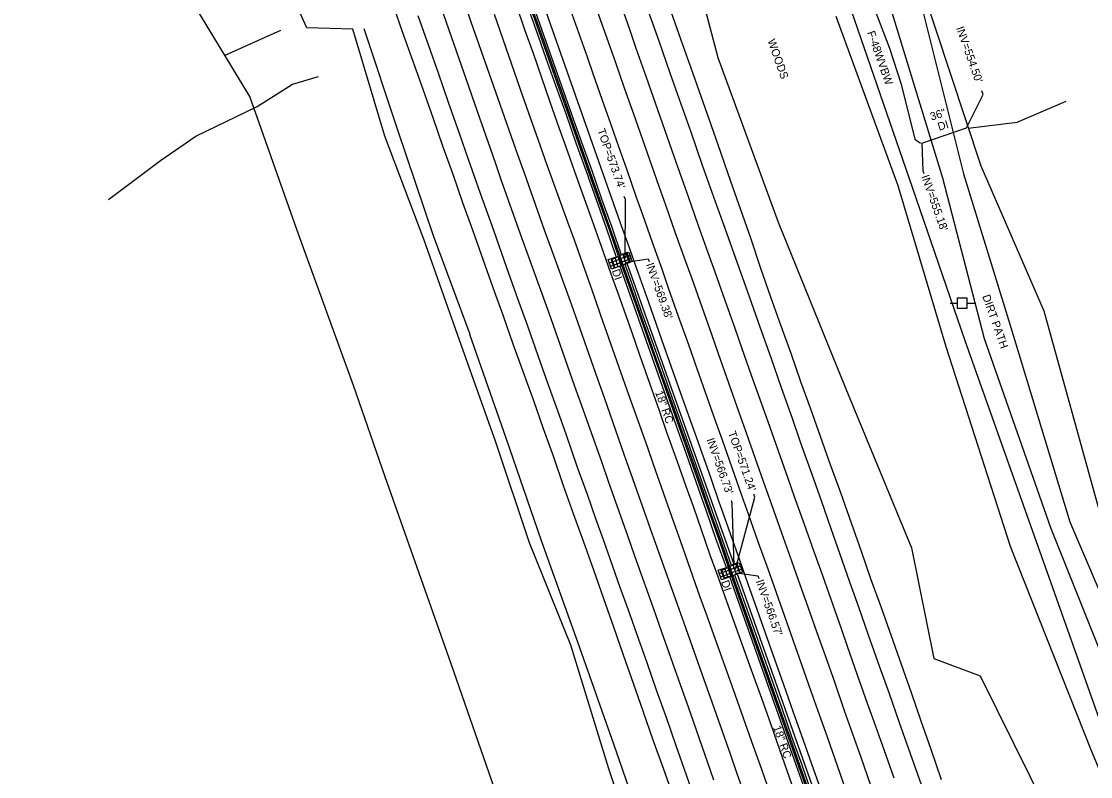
# Model space of a CAD drawing. Extents: x 2004847 to 2009016, y 1134161 to 1140101.
# Drawn here: x 2005873 to 2006408, y 1136162 to 1136539 of the extents above; entities that cross this region are included whole.
import ezdxf

# ---------------------------------------------------------------- set-up
doc = ezdxf.new("R2010")
doc.units = 0
for name, color, linetype in [('RD_EX_Conc', 7, 'Continuous'), ('RD_EX_DR_Inlet', 7, 'Continuous'), ('RD_EX_DR_Inlet_txCode', 7, 'Continuous'), ('RD_EX_DR_Pipe', 7, 'Continuous'), ('RD_EX_DR_Pipe_txCode', 7, 'Continuous'), ('RD_EX_Driveway', 7, 'Continuous'), ('RD_EX_Fence_Other', 7, 'Continuous'), ('RD_EX_H2O', 7, 'Continuous'), ('RD_EX_Pavement_Markings', 7, 'Continuous'), ('RD_EX_Road', 7, 'Continuous'), ('RD_EX_UT', 7, 'Continuous'), ('RD_EX_VEG', 7, 'Continuous'), ('RD_Sketch3', 7, 'Continuous')]:
    doc.layers.add(name, color=color, linetype=linetype)

msp = doc.modelspace()

# ---------------------------------------------------------------- linework, layer by layer
at = {"layer": 'RD_EX_Conc'}
for points in [[(2006126.82, 1136548.76), (2006131.84, 1136534.6), (2006136.85, 1136520.47), (2006141.87, 1136506.33), (2006146.87, 1136492.19), (2006151.89, 1136478.06), (2006156.89, 1136463.92), (2006161.94, 1136449.8), (2006166.95, 1136435.61), (2006171.9, 1136421.48), (2006176.97, 1136407.37), (2006181.96, 1136393.22), (2006186.97, 1136379.09), (2006191.97, 1136364.99), (2006197.01, 1136350.77), (2006202, 1136336.67), (2006206.99, 1136322.55), (2006212.01, 1136308.42), (2006216.96, 1136294.26), (2006221.99, 1136280.14), (2006226.92, 1136265.96), (2006231.91, 1136251.8), (2006236.91, 1136237.66), (2006241.89, 1136223.49), (2006246.86, 1136209.37), (2006251.86, 1136195.19), (2006256.85, 1136181.1), (2006261.87, 1136166.89), (2006266.82, 1136152.8)], [(2006127.45, 1136548.98), (2006132.48, 1136534.83), (2006137.49, 1136520.69), (2006142.48, 1136506.55), (2006147.52, 1136492.42), (2006152.53, 1136478.29), (2006157.53, 1136464.14), (2006162.56, 1136450.02), (2006167.57, 1136435.83), (2006172.54, 1136421.71), (2006177.6, 1136407.59), (2006182.59, 1136393.44), (2006187.59, 1136379.31), (2006192.59, 1136365.21), (2006197.65, 1136351.01), (2006202.62, 1136336.89), (2006207.63, 1136322.77), (2006212.62, 1136308.63), (2006217.58, 1136294.48), (2006222.62, 1136280.35), (2006227.56, 1136266.18), (2006232.54, 1136252.02), (2006237.53, 1136237.88), (2006242.53, 1136223.72), (2006247.51, 1136209.6), (2006252.51, 1136195.42), (2006257.53, 1136181.34), (2006262.53, 1136167.13), (2006267.48, 1136153.03)]]:
    msp.add_lwpolyline(points, dxfattribs=at)
at = {"layer": 'RD_EX_DR_Inlet'}
for p, q in [((2006175.57, 1136423.28), (2006177.19, 1136418.55)), ((2006167.31, 1136418.47), (2006172.04, 1136420.09)), ((2006167.86, 1136416.86), (2006172.59, 1136418.48)), ((2006168.37, 1136420.63), (2006169.99, 1136415.9)), ((2006169.98, 1136421.18), (2006171.6, 1136416.45)), ((2006172.9, 1136420.57), (2006177.63, 1136422.19)), ((2006173.45, 1136418.96), (2006178.18, 1136420.58)), ((2006173.96, 1136422.73), (2006175.58, 1136418)), ((2006230.66, 1136268.04), (2006232.28, 1136263.31)), ((2006222.23, 1136263.18), (2006226.96, 1136264.8)), ((2006222.79, 1136261.57), (2006227.52, 1136263.19)), ((2006223.29, 1136265.34), (2006224.91, 1136260.61)), ((2006224.9, 1136265.89), (2006226.52, 1136261.16)), ((2006227.99, 1136265.33), (2006232.72, 1136266.95)), ((2006228.54, 1136263.72), (2006233.27, 1136265.35)), ((2006229.05, 1136267.49), (2006230.67, 1136262.76))]:
    msp.add_line(p, q, dxfattribs=at)
for points in [[(2006173.97, 1136417.45), (2006172.35, 1136422.18), (2006177.08, 1136423.8), (2006178.7, 1136419.07)], [(2006168.38, 1136415.35), (2006166.76, 1136420.08), (2006171.49, 1136421.7), (2006173.11, 1136416.97)], [(2006229.06, 1136262.21), (2006227.44, 1136266.94), (2006232.17, 1136268.56), (2006233.79, 1136263.83)], [(2006223.31, 1136260.06), (2006221.68, 1136264.79), (2006226.41, 1136266.41), (2006228.03, 1136261.68)]]:
    msp.add_lwpolyline(points, close=True, dxfattribs=at)
at = {"layer": 'RD_EX_DR_Inlet_txCode'}
for points in [[(2006345.77, 1136485.85), (2006354.14, 1136502.56), (2006353.5, 1136504.37)], [(2006323.46, 1136478.34), (2006324.03, 1136464.51), (2006324.52, 1136463.11)], [(2006175.25, 1136420.54), (2006175.32, 1136450.13), (2006174.77, 1136451.67)], [(2006175.89, 1136418.77), (2006186.64, 1136420.47), (2006187.11, 1136419.14)], [(2006230.32, 1136265.36), (2006240, 1136301.41), (2006239.48, 1136302.88)], [(2006229.63, 1136267.31), (2006228.65, 1136298.35), (2006228.26, 1136299.45)], [(2006230.99, 1136263.47), (2006241.48, 1136261.95), (2006241.93, 1136260.68)]]:
    msp.add_lwpolyline(points, dxfattribs=at)
at = {"layer": 'RD_EX_DR_Pipe'}
for p, q in [((2006323.46, 1136478.34), (2006345.77, 1136485.85)), ((2006175.89, 1136418.77), (2006229.63, 1136267.31)), ((2006230.99, 1136263.47), (2006287.37, 1136104.14))]:
    msp.add_line(p, q, dxfattribs=at)
at = {"layer": 'RD_EX_Driveway'}
for points in [[(2006320.55, 1136558.36), (2006344.22, 1136462.95), (2006367.47, 1136387.76), (2006397.5, 1136288.99), (2006440.84, 1136187.25), (2006478.74, 1136083.47), (2006518.32, 1135988.65), (2006563.43, 1135904.15)], [(2006551.41, 1135897.85), (2006505.13, 1135983.38), (2006469.38, 1136080.46), (2006429.34, 1136182.74), (2006387.99, 1136286.09), (2006354.86, 1136380.53), (2006334.03, 1136460.8), (2006306.37, 1136551.19)]]:
    msp.add_lwpolyline(points, dxfattribs=at)
at = {"layer": 'RD_EX_Fence_Other'}
for points in [[(2006150.07, 1136043.34), (2006115.42, 1136139.93), (2006088.15, 1136218.09), (2006055.25, 1136311.48), (2006039.49, 1136357.1), (2006011.97, 1136432.75), (2005987.61, 1136501.5), (2005957.81, 1136550.91), (2005937.54, 1136641.63), (2005905.9, 1136732.88), (2005873.43, 1136823.78)], [(2006288.09, 1136544.58), (2006318.68, 1136456.24), (2006344.96, 1136379.7), (2006379.57, 1136282.04), (2006416.49, 1136178.27), (2006490.52, 1135969.29)]]:
    msp.add_lwpolyline(points, dxfattribs=at)
at = {"layer": 'RD_EX_H2O'}
msp.add_line((2005975.27, 1136522.16), (2006003.16, 1136534.73), dxfattribs=at)
for points in [[(2006272.18, 1136630.95), (2006272.22, 1136630.81), (2006281.18, 1136599.43), (2006285.93, 1136585.09), (2006298.47, 1136548.7), (2006307.39, 1136525.67), (2006313.2, 1136507.7), (2006320, 1136480.19), (2006322.75, 1136478.28)], [(2006044.58, 1136535.51), (2006061.38, 1136484.99), (2006079.26, 1136432.16), (2006097.52, 1136382.87), (2006097.47, 1136382.84), (2006115.58, 1136331.03), (2006133.19, 1136279.75), (2006151.31, 1136229.01), (2006169.58, 1136177.63)], [(2005917.01, 1136450.16), (2005943.01, 1136469.65), (2005960.66, 1136481.73), (2005991.29, 1136496.61), (2006008.97, 1136507.77), (2006021.87, 1136511.55)], [(2006346.55, 1136485.76), (2006371.1, 1136488.8), (2006395.68, 1136499.17)], [(2006169.58, 1136177.63), (2006207.33, 1136068.49), (2006240.4, 1135975.91), (2006259.05, 1135923.24), (2006279.18, 1135873.19), (2006283.21, 1135863.56), (2006290.81, 1135841.34), (2006301.16, 1135806.7), (2006317.11, 1135762.46), (2006327.77, 1135727.04)]]:
    msp.add_lwpolyline(points, dxfattribs=at)
at = {"layer": 'RD_EX_Pavement_Markings'}
for points in [[(2006144.73, 1136553.93), (2006150.43, 1136537.67), (2006156.13, 1136521.4), (2006159.25, 1136512.51), (2006163.57, 1136500.28), (2006167.89, 1136488.04), (2006170.88, 1136479.37), (2006175.81, 1136465.36), (2006180.73, 1136451.35), (2006183.81, 1136442.6), (2006188.71, 1136428.81), (2006193.61, 1136415.02), (2006196.74, 1136406.02), (2006201.76, 1136391.81), (2006206.78, 1136377.61), (2006210.03, 1136368.49), (2006215.21, 1136353.78), (2006220.39, 1136339.08), (2006223.62, 1136329.98), (2006228.52, 1136316.19), (2006233.41, 1136302.39), (2006236.7, 1136293.05), (2006241.58, 1136279.27), (2006246.46, 1136265.49), (2006249.42, 1136256.95), (2006254.79, 1136241.81), (2006260.16, 1136226.68), (2006263.11, 1136218.23), (2006268.05, 1136204.31), (2006272.98, 1136190.39), (2006276.1, 1136181.52), (2006281.31, 1136166.68), (2006286.53, 1136151.84)], [(2006094.82, 1136548.31), (2006098.06, 1136538.91), (2006108.27, 1136510.01), (2006111.6, 1136500.62), (2006121.45, 1136472.59), (2006124.73, 1136463.39), (2006134.78, 1136434.88), (2006138.15, 1136425.46), (2006148.31, 1136397.39), (2006151.49, 1136388.46), (2006161.41, 1136360.52), (2006164.68, 1136351.15), (2006174.59, 1136322.82), (2006177.93, 1136313.43), (2006187.67, 1136285.66), (2006190.94, 1136276.4), (2006201.13, 1136247.8), (2006204.48, 1136238.58), (2006214.54, 1136210.17), (2006217.63, 1136201.33), (2006227.6, 1136173.06), (2006230.87, 1136163.75), (2006241.16, 1136134.53)], [(2006120.32, 1136548.39), (2006125.13, 1136534.55), (2006129.17, 1136523.28), (2006133.34, 1136511.03), (2006137.41, 1136499.38), (2006141.28, 1136488.41), (2006146.42, 1136474.04), (2006149.89, 1136464.14), (2006153.05, 1136455.29), (2006159.33, 1136437.53), (2006164.18, 1136424.02), (2006168.11, 1136413.02), (2006172.69, 1136400.13), (2006178.3, 1136384.11), (2006182.44, 1136372.43), (2006187.42, 1136358.29), (2006192.23, 1136344.7), (2006195.76, 1136334.4), (2006201.24, 1136319.12), (2006205.48, 1136306.87), (2006209.28, 1136296.33), (2006213.18, 1136285.12), (2006217.59, 1136272.54), (2006221.46, 1136261.77), (2006225.06, 1136251.7), (2006229.06, 1136240.56), (2006233.53, 1136228.01), (2006238.18, 1136215.12), (2006243.26, 1136200.88), (2006247.76, 1136188.26), (2006252.54, 1136174.66), (2006255.84, 1136165.21), (2006259.8, 1136153.76)], [(2006134.46, 1136547.45), (2006172.52, 1136438.91), (2006176.48, 1136427.89), (2006181.66, 1136413.28), (2006186.64, 1136399.28), (2006193.39, 1136380.22), (2006198.19, 1136366.4), (2006203.73, 1136351.06), (2006210.69, 1136331.44), (2006217.96, 1136310.78), (2006222.07, 1136299.06), (2006223.98, 1136293.57), (2006227.92, 1136282.63), (2006232.32, 1136270.05), (2006236.53, 1136258.1), (2006241, 1136245.44), (2006245.17, 1136233.6), (2006249.85, 1136220.44), (2006254.32, 1136207.72), (2006259.07, 1136194.42), (2006264.11, 1136179.95), (2006268.38, 1136168.14), (2006275.31, 1136148.35)], [(2006172.29, 1136549.4), (2006177.28, 1136535.18), (2006180.53, 1136525.73), (2006185.44, 1136511.81), (2006190.35, 1136497.89), (2006193.67, 1136488.4), (2006198.52, 1136474.66), (2006203.36, 1136460.93), (2006206.62, 1136451.54), (2006211.53, 1136437.57), (2006216.44, 1136423.6), (2006219.94, 1136414.01), (2006224.95, 1136399.88), (2006229.95, 1136385.74), (2006233.28, 1136376.09), (2006238.19, 1136362.33), (2006243.09, 1136348.57), (2006246.42, 1136339.11), (2006251.46, 1136325.02), (2006256.5, 1136310.92), (2006259.72, 1136301.75), (2006264.61, 1136287.93), (2006269.51, 1136274.11), (2006272.78, 1136264.98), (2006277.95, 1136250.35), (2006283.13, 1136235.72), (2006286.22, 1136226.83), (2006291.2, 1136212.63), (2006296.18, 1136198.43), (2006299.5, 1136189.27), (2006304.5, 1136175.2), (2006309.51, 1136161.14)], [(2006071.6, 1136542.04), (2006076.82, 1136527), (2006081.69, 1136513.37), (2006086.77, 1136498.83), (2006092.19, 1136483.34), (2006096.73, 1136470.22), (2006102.72, 1136453.32), (2006109.31, 1136434.78), (2006115.94, 1136416.07), (2006121.35, 1136400.69), (2006126.33, 1136386.95), (2006131.58, 1136372.08), (2006136.62, 1136357.91), (2006141.37, 1136344.65), (2006145.67, 1136332.43), (2006151.09, 1136316.81), (2006156.17, 1136302.78), (2006160.44, 1136290.73), (2006164.17, 1136280.26), (2006168.81, 1136266.94), (2006172.55, 1136256.37), (2006176.65, 1136244.96), (2006181.93, 1136230.32), (2006186, 1136218.71), (2006190.71, 1136205.14), (2006195.96, 1136190.37), (2006200.53, 1136177.21), (2006205.64, 1136162.64), (2006211.09, 1136147.29)], [(2006083.86, 1136543.99), (2006087.01, 1136534.95), (2006096.94, 1136506.67), (2006100.08, 1136497.52), (2006110.03, 1136469.13), (2006113.1, 1136460.1), (2006123.56, 1136430.67), (2006126.66, 1136421.9), (2006136.98, 1136393.53), (2006140.15, 1136384.4), (2006149.95, 1136356.8), (2006153.2, 1136347.59), (2006163.49, 1136318.61), (2006166.73, 1136309.3), (2006176.49, 1136281.61), (2006179.72, 1136272.58), (2006190.17, 1136243.18), (2006193.41, 1136234.07), (2006203.49, 1136205.46), (2006206.67, 1136196.54), (2006216.23, 1136169.19), (2006219.41, 1136160.03)], [(2006109.64, 1136542.66), (2006119.64, 1136513.92), (2006122.87, 1136504.7), (2006132.7, 1136476.85), (2006136.02, 1136467.44), (2006146.41, 1136438.95), (2006149.64, 1136429.93), (2006159.64, 1136401.64), (2006162.9, 1136392.35), (2006172.87, 1136364.06), (2006176.1, 1136355.01), (2006186.14, 1136326.68), (2006189.27, 1136317.76), (2006199.32, 1136289.08), (2006202.62, 1136279.66), (2006212.58, 1136251.61), (2006215.87, 1136242.56), (2006226.05, 1136214.05), (2006229.15, 1136205.28), (2006239.22, 1136176.84), (2006242.45, 1136167.72), (2006252.54, 1136139.29)], [(2006161.69, 1136542.91), (2006166.84, 1136528.35), (2006170.15, 1136519.04), (2006174.74, 1136505.94), (2006179.33, 1136492.84), (2006182.68, 1136483.36), (2006187.35, 1136470.09), (2006192.02, 1136456.81), (2006195.35, 1136447.36), (2006200.25, 1136433.51), (2006205.15, 1136419.66), (2006208.44, 1136410.58), (2006213.45, 1136396.46), (2006218.46, 1136382.33), (2006221.66, 1136373.22), (2006226.86, 1136358.53), (2006232.05, 1136343.84), (2006235.29, 1136334.45), (2006240.17, 1136320.71), (2006245.05, 1136306.98), (2006248.28, 1136297.65), (2006253.29, 1136283.56), (2006258.3, 1136269.46), (2006261.51, 1136260.5), (2006266.66, 1136245.97), (2006271.81, 1136231.44), (2006275.13, 1136222.15), (2006279.92, 1136208.48), (2006284.71, 1136194.81), (2006288.05, 1136185.35), (2006292.95, 1136171.41), (2006297.85, 1136157.46)], [(2006323.36, 1136157.6), (2006317.84, 1136173.05), (2006312.36, 1136188.5), (2006307.08, 1136203.61), (2006302.5, 1136216.4), (2006296.85, 1136232.45), (2006291.97, 1136246.29), (2006287.53, 1136258.94), (2006282.49, 1136273.21), (2006278.12, 1136285.56), (2006273.27, 1136299.46), (2006268.6, 1136312.69), (2006263.05, 1136328.37), (2006258.77, 1136340.66), (2006253.38, 1136355.96), (2006248.1, 1136370.9), (2006242.65, 1136386.25), (2006237.3, 1136401.5), (2006232.12, 1136415.93), (2006225.23, 1136435.56), (2006220.38, 1136448.98), (2006213.76, 1136467.6), (2006208.14, 1136483.82), (2006202.39, 1136500.07), (2006197.68, 1136513.3), (2006192.13, 1136529.22), (2006186.85, 1136544.1)]]:
    msp.add_lwpolyline(points, dxfattribs=at)
at = {"layer": 'RD_EX_Road'}
msp.add_line((2006223.14, 1136264.76), (2006225.88, 1136265.8), dxfattribs=at)
for points in [[(2006117.95, 1136578.72), (2006118.33, 1136577.63), (2006123.3, 1136563.48), (2006128.35, 1136549.35), (2006133.36, 1136535.21), (2006138.37, 1136521.07), (2006143.36, 1136506.93), (2006148.41, 1136492.81), (2006153.45, 1136478.68), (2006158.59, 1136464.59), (2006163.42, 1136450.39), (2006168.46, 1136436.23), (2006173.24, 1136422.52)], [(2006115.39, 1136577.85), (2006115.54, 1136577.38), (2006120.52, 1136563.22), (2006125.58, 1136549.07), (2006130.6, 1136534.99), (2006135.61, 1136520.77), (2006140.62, 1136506.67), (2006145.63, 1136492.55), (2006150.53, 1136478.4), (2006155.62, 1136464.29), (2006160.66, 1136450.15), (2006165.63, 1136436.02), (2006170.61, 1136421.87), (2006170.87, 1136421.15)], [(2006059.15, 1136547.64), (2006063.98, 1136533.49), (2006069.02, 1136519.26), (2006074.12, 1136505.23), (2006079.05, 1136491.06), (2006083.87, 1136476.9), (2006089.01, 1136462.73), (2006093.91, 1136448.54), (2006099.13, 1136434.48), (2006104.1, 1136420.34), (2006109.05, 1136406.2), (2006114.18, 1136392.01), (2006119.11, 1136377.94), (2006124.24, 1136363.81), (2006129.37, 1136349.7), (2006134.29, 1136335.58), (2006139.3, 1136321.5), (2006144.22, 1136307.19), (2006149.22, 1136293.12), (2006154.31, 1136278.99), (2006159.38, 1136264.95), (2006164.41, 1136250.72), (2006169.38, 1136236.56), (2006174.26, 1136222.47), (2006179.16, 1136208.33), (2006184.14, 1136194.11), (2006189.09, 1136180.02), (2006194.18, 1136165.88), (2006199.25, 1136151.73)], [(2006197.99, 1136544.13), (2006202.99, 1136529.93), (2006207.97, 1136515.85), (2006212.99, 1136501.7), (2006217.95, 1136487.54), (2006222.98, 1136473.33), (2006227.9, 1136459.26), (2006232.83, 1136445.14), (2006237.76, 1136430.89), (2006242.86, 1136415.79), (2006247.75, 1136401.54), (2006252.82, 1136387.46), (2006257.94, 1136373.35), (2006262.87, 1136359.18), (2006267.59, 1136346), (2006272.6, 1136331.81), (2006277.59, 1136317.73), (2006282.9, 1136303.7), (2006288.09, 1136288.57), (2006293.11, 1136274.43), (2006298.06, 1136260.25), (2006303.09, 1136246.14), (2006308.17, 1136232.02), (2006313.06, 1136217.89), (2006318.07, 1136203.68), (2006322.97, 1136189.56), (2006327.95, 1136175.43), (2006333.21, 1136160.31)], [(2006174.97, 1136417.71), (2006177.86, 1136418.84), (2006176.24, 1136423.56), (2006173.24, 1136422.52)], [(2006170.87, 1136421.15), (2006168.27, 1136420.03), (2006169.67, 1136415.89), (2006172.45, 1136416.74)], [(2006174.97, 1136417.71), (2006178.46, 1136407.96), (2006183.44, 1136393.82), (2006188.45, 1136379.68), (2006193.47, 1136365.58), (2006198.49, 1136351.38), (2006203.46, 1136337.26), (2006208.45, 1136323.13), (2006213.47, 1136309), (2006218.49, 1136294.88), (2006223.48, 1136280.73), (2006228.22, 1136267.33)], [(2006172.45, 1136416.74), (2006175.68, 1136407.74), (2006180.68, 1136393.58), (2006185.66, 1136379.45), (2006190.69, 1136365.31), (2006195.69, 1136351.18), (2006200.71, 1136336.99), (2006205.67, 1136322.92), (2006210.68, 1136308.71), (2006215.6, 1136294.56), (2006220.59, 1136280.42), (2006225.67, 1136266.36), (2006225.88, 1136265.8)], [(2006229.89, 1136262.56), (2006232.64, 1136263.5), (2006230.99, 1136268.33), (2006228.22, 1136267.33)], [(2006227.36, 1136261.64), (2006224.65, 1136260.79), (2006223.14, 1136264.76)], [(2006227.36, 1136261.64), (2006230.66, 1136252.21), (2006235.69, 1136238.07), (2006240.66, 1136223.94), (2006245.65, 1136209.78), (2006250.61, 1136195.62), (2006255.61, 1136181.46), (2006260.63, 1136167.31), (2006265.59, 1136153.2), (2006270.58, 1136139.03), (2006275.54, 1136124.85), (2006280.51, 1136110.73), (2006283.22, 1136103.07)], [(2006229.89, 1136262.56), (2006233.47, 1136252.43), (2006238.49, 1136238.31), (2006243.5, 1136224.15), (2006248.45, 1136210.01), (2006253.42, 1136195.84), (2006258.41, 1136181.74), (2006263.44, 1136167.55), (2006268.39, 1136153.44), (2006273.39, 1136139.29), (2006278.37, 1136125.14), (2006283.39, 1136111), (2006285.76, 1136104.24)]]:
    msp.add_lwpolyline(points, dxfattribs=at)
at = {"layer": 'RD_EX_UT'}
for p, q in [((2006337.71, 1136398.32), (2006341.18, 1136398.32)), ((2006346.14, 1136400.88), (2006341.14, 1136400.88)), ((2006341.14, 1136400.88), (2006341.14, 1136395.88)), ((2006346.07, 1136398.32), (2006349.71, 1136398.32)), ((2006346.14, 1136395.88), (2006346.14, 1136400.88)), ((2006341.14, 1136395.88), (2006346.14, 1136395.88))]:
    msp.add_line(p, q, dxfattribs=at)
at = {"layer": 'RD_EX_VEG'}
for points in [[(2006061.81, 1137035.33), (2006055.47, 1136986.65), (2006066.5, 1136947.96), (2006098.85, 1136862.24), (2006126.13, 1136771.44), (2006157.91, 1136698.56), (2006202.97, 1136591.32), (2006221.46, 1136521.07)], [(2006039.1, 1136535.19), (2006016.14, 1136535.95), (2005996.66, 1136579.1), (2005983.98, 1136625.63), (2005975.17, 1136673.57), (2005961.75, 1136717.89)], [(2006322.66, 1136558.8), (2006353.02, 1136466.99), (2006384.47, 1136394.39), (2006412, 1136295.24), (2006443.56, 1136188.55), (2006484.2, 1136085.12), (2006524.25, 1135990.06), (2006569.76, 1135908.33), (2006606.1, 1135833.79)], [(2006565.48, 1135819.09), (2006528.32, 1135891.1), (2006489.01, 1135976.52), (2006450.61, 1136073.8), (2006408.25, 1136174.58), (2006367.76, 1136276.74), (2006335.67, 1136376.41), (2006311.68, 1136456.94), (2006280.68, 1136541.58)], [(2006167.02, 1136165.56), (2006148.07, 1136227.41), (2006127.34, 1136278.53), (2006110.59, 1136328.91), (2006092.36, 1136379.73), (2006074.81, 1136429.85), (2006055.15, 1136481.77), (2006039.1, 1136535.19)], [(2006221.46, 1136521.07), (2006251.63, 1136438.73), (2006285.47, 1136355.47), (2006318.32, 1136276), (2006329.42, 1136220.78)], [(2006329.42, 1136220.78), (2006352.55, 1136212.1), (2006402.65, 1136111.04), (2006430.53, 1136031.48), (2006451.57, 1135942.9), (2006478.35, 1135898.12), (2006513.78, 1135860.32), (2006547.83, 1135768.67), (2006577.61, 1135717.06), (2006602.57, 1135668.11), (2006642.32, 1135585.7)], [(2006322.5, 1135727.67), (2006311.4, 1135759.47), (2006298.58, 1135765.44), (2006298.64, 1135791.57), (2006297.71, 1135804.25), (2006283.46, 1135839.35), (2006274.08, 1135862.69), (2006250.13, 1135919.86), (2006228.17, 1135978.51), (2006200.66, 1136064.46), (2006167.02, 1136165.56)]]:
    msp.add_lwpolyline(points, dxfattribs=at)

# ---------------------------------------------------------------- texts
at = {"layer": 'RD_EX_DR_Inlet_txCode'}
for s, p in [("INV=554.50'", (2006340.54, 1136535.8)), ("TOP=573.74'", (2006161.2, 1136484.76)), ("INV=555.18'", (2006323.16, 1136461.61)), ("INV=569.38'", (2006185.57, 1136417.66)), ('DI', (2006168.47, 1136414.49)), ("TOP=571.24'", (2006226.56, 1136333.54)), ("INV=566.73'", (2006215.83, 1136330.14)), ('DI', (2006223.09, 1136259.02)), ("INV=566.57'", (2006240.44, 1136259.36))]:
    msp.add_text(s, height=4, rotation=289.4494, dxfattribs=at).set_placement(p)
at = {"layer": 'RD_EX_DR_Pipe_txCode'}
for s, rotation, p in [('36"', 17.2613, (2006328.32, 1136489.53)), ('DI', 17.2613, (2006332.12, 1136484.43)), ('18" RC', 289.4494, (2006190.11, 1136353.77)), ('18" RC', 289.4494, (2006249.06, 1136186.36))]:
    msp.add_text(s, height=4, rotation=rotation, dxfattribs=at).set_placement(p)
at = {"layer": 'RD_Sketch3'}
for s, p in [('WOODS', (2006246.27, 1136529.5)), ('F-48WVBW', (2006296.03, 1136533.56)), ('DIRT PATH', (2006353.61, 1136401.8))]:
    msp.add_text(s, height=4, rotation=289.4494, dxfattribs=at).set_placement(p)

doc.saveas('drawing.dxf')
